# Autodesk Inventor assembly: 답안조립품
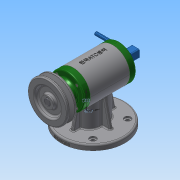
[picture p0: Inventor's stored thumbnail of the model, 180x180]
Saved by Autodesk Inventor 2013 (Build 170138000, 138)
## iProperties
Created: 2017-02
Part Number: 답안조립품
Document SubType Name: Assembly
Designer: Administrator
Author: Administrator
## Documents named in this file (16)
- C:\Users\Administrator\Desktop\370208V1023\답안조립품.iam
- C:\Users\Administrator\Desktop\370208V1023\본체.ipt
- C:\Users\Administrator\Desktop\370208V1023\멈춤나사 M3x8.ipt
- C:\Users\Administrator\Desktop\370208V1023\키 4 x 4 x 18.ipt
- C:\Users\Administrator\Desktop\370208V1023\편심축.ipt
- C:\Users\Administrator\Desktop\370208V1023\베어링 6201.ipt
- C:\Users\Administrator\Desktop\370208V1023\앞커버.ipt
- C:\Users\Administrator\Desktop\370208V1023\오일실 12 22 7.ipt
- C:\Users\Administrator\Desktop\370208V1023\볼트 M3x0.5x8.ipt
- C:\Users\Administrator\Desktop\370208V1023\V벨트풀리.ipt
- C:\Users\Administrator\Desktop\370208V1023\베어링 6202.ipt
- C:\Users\Administrator\Desktop\370208V1023\뒤커버.ipt
- C:\Users\Administrator\Desktop\370208V1023\레버.ipt
- C:\Users\Administrator\Desktop\370208V1023\가변스프링.ipt
- C:\Users\Administrator\Desktop\370208V1023\슬라이드.ipt
- C:\Users\Administrator\Desktop\370208V1023\본체상부커버.ipt
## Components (2 placed, 2 different names)
1. V벨트풀리:1
2. 가변스프링:1
